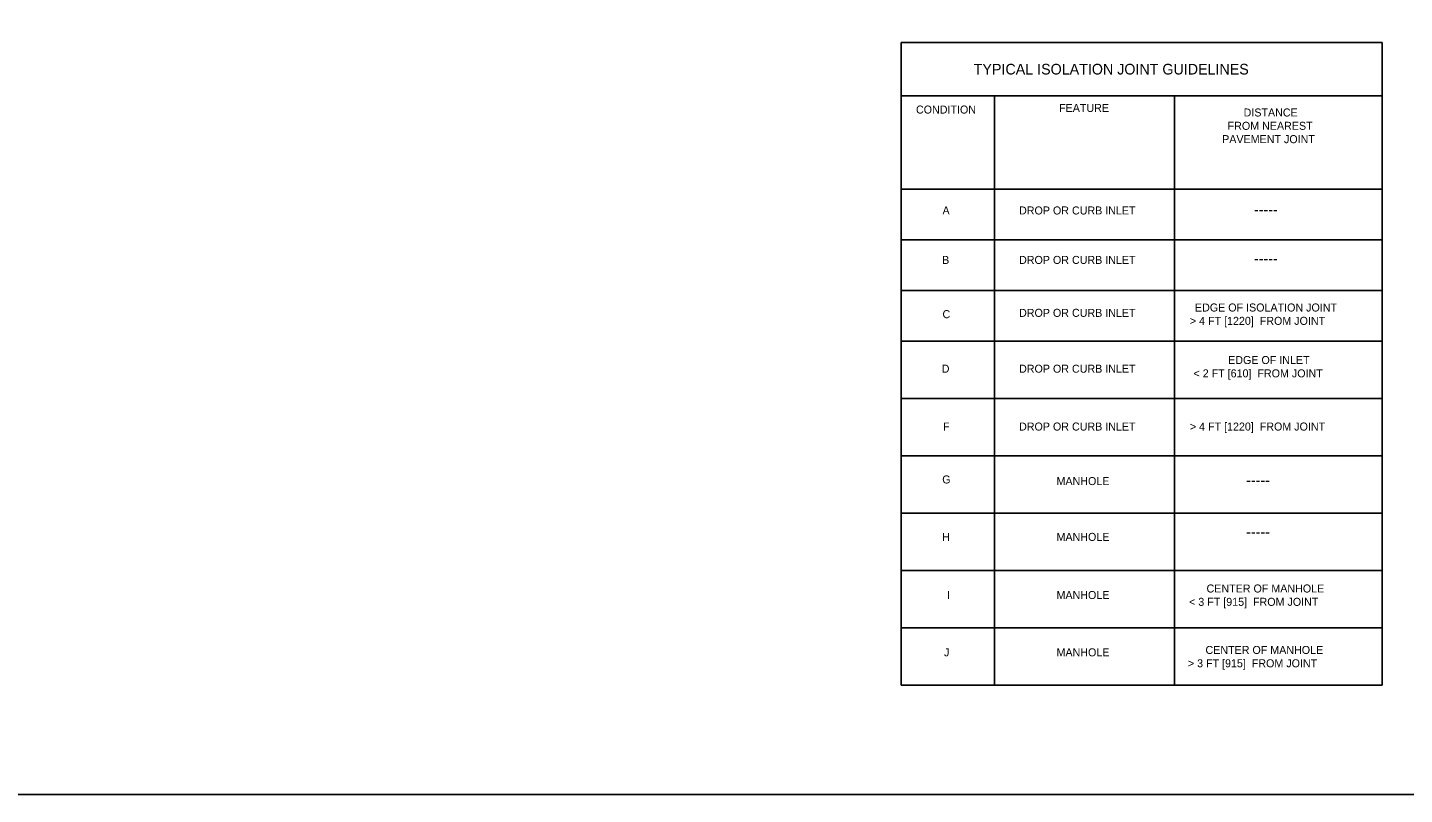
# Model space of a CAD drawing. Extents: x 49991.4 to 50029.7, y 49987.6 to 50011.4.
# Drawn here: x 49999.92 to 50010.24, y 49987.8 to 49993.55 of the extents above; entities that cross this region are included whole.
import ezdxf

# ---------------------------------------------------------------- set-up
doc = ezdxf.new("R2010")
doc.units = 0
doc.layers.add('Level 1', color=7, linetype='Continuous')
doc.layers.add('Level 2', color=7, linetype='Continuous')

msp = doc.modelspace()

# ---------------------------------------------------------------- linework, layer by layer
at = {"layer": 'Level 1'}
msp.add_lwpolyline([(49999.384, 49998.999), (50016.75, 49998.999), (50016.75, 49987.799), (49999.384, 49987.799)], close=True, dxfattribs=at)
at = {"layer": 'Level 2'}
for p, q in [((50010.073, 49993.44), (50010.073, 49988.62)), ((50006.467, 49988.62), (50006.467, 49993.04)), ((50006.467, 49993.04), (50010.073, 49993.04)), ((50007.167, 49993.04), (50007.167, 49988.62)), ((50008.517, 49993.04), (50008.517, 49988.62)), ((50010.073, 49993.04), (50010.073, 49988.62)), ((50006.467, 49992.34), (50010.073, 49992.34)), ((50006.467, 49991.96), (50010.073, 49991.96)), ((50006.467, 49991.58), (50010.073, 49991.58)), ((50006.467, 49991.2), (50010.073, 49991.2)), ((50006.467, 49990.77), (50010.073, 49990.77)), ((50006.467, 49990.77), (50010.073, 49990.77)), ((50006.467, 49990.34), (50010.073, 49990.34)), ((50006.467, 49989.91), (50010.073, 49989.91)), ((50006.467, 49989.48), (50010.073, 49989.48)), ((50006.467, 49989.05), (50010.073, 49989.05)), ((50010.073, 49988.62), (50006.467, 49988.62))]:
    msp.add_line(p, q, dxfattribs=at)
msp.add_lwpolyline([(50010.073, 49993.04), (50006.467, 49993.04), (50006.467, 49993.44), (50010.073, 49993.44)], dxfattribs=at)

# ---------------------------------------------------------------- texts
for s, height, p in [('TYPICAL ISOLATION JOINT GUIDELINES', 0.08, (50007.011, 49993.2)), ('CONDITION', 0.06, (50006.578, 49992.907)), ('FEATURE', 0.06, (50007.651, 49992.919)), ('DISTANCE', 0.06, (50009.035, 49992.885)), ('FROM NEAREST', 0.06, (50008.915, 49992.785)), ('PAVEMENT JOINT', 0.06, (50008.874, 49992.685)), ('A', 0.06, (50006.777, 49992.15)), ('DROP OR CURB INLET', 0.06, (50007.351, 49992.15)), ('-----', 0.08, (50009.113, 49992.147)), ('B', 0.06, (50006.774, 49991.779)), ('DROP OR CURB INLET', 0.06, (50007.351, 49991.779)), ('-----', 0.08, (50009.113, 49991.78)), ('DROP OR CURB INLET', 0.06, (50007.351, 49991.382)), ('EDGE OF ISOLATION JOINT', 0.06, (50008.67, 49991.422)), ('C', 0.06, (50006.777, 49991.372)), ('> 4 FT [1220]  FROM JOINT', 0.06, (50008.632, 49991.322)), ('EDGE OF INLET', 0.06, (50008.919, 49991.028)), ('D', 0.06, (50006.771, 49990.963)), ('DROP OR CURB INLET', 0.06, (50007.351, 49990.963)), ('< 2 FT [610]  FROM JOINT', 0.06, (50008.659, 49990.928)), ('F', 0.06, (50006.781, 49990.529)), ('DROP OR CURB INLET', 0.06, (50007.351, 49990.529)), ('> 4 FT [1220]  FROM JOINT', 0.06, (50008.632, 49990.529)), ('G', 0.06, (50006.775, 49990.132)), ('MANHOLE', 0.06, (50007.632, 49990.12)), ('-----', 0.08, (50009.054, 49990.117)), ('H', 0.06, (50006.773, 49989.701)), ('MANHOLE', 0.06, (50007.632, 49989.701)), ('-----', 0.08, (50009.054, 49989.73)), ('I', 0.06, (50006.811, 49989.265)), ('MANHOLE', 0.06, (50007.632, 49989.265)), ('< 3 FT [915]  FROM JOINT', 0.06, (50008.626, 49989.214)), ('CENTER OF MANHOLE', 0.06, (50008.757, 49989.314)), ('J', 0.06, (50006.788, 49988.835)), ('MANHOLE', 0.06, (50007.632, 49988.835)), ('CENTER OF MANHOLE', 0.06, (50008.749, 49988.853)), ('> 3 FT [915]  FROM JOINT', 0.06, (50008.617, 49988.753))]:
    msp.add_text(s, height=height, dxfattribs=at).set_placement(p)

doc.saveas('drawing.dxf')
